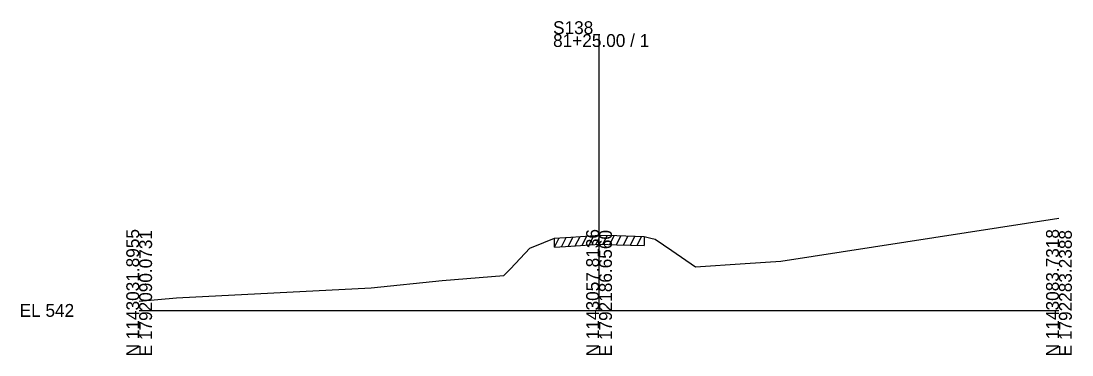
# Model space of a CAD drawing. Extents: x -26 to 1203, y -10 to 19606.
# Drawn here: x -25.7 to 202.8, y 2490.3 to 2562.9 of the extents above; entities that cross this region are included whole.
import ezdxf

# ---------------------------------------------------------------- set-up
doc = ezdxf.new("R2010")
doc.units = 0
for name, color, linetype in [('RD_EX_Driveway', 7, 'Continuous'), ('RD_GPK_XS_Cell', 7, 'Continuous'), ('RD_XS_ExGround', 7, 'Continuous'), ('RD_XS_ExPaveRet', 7, 'Continuous')]:
    doc.layers.add(name, color=color, linetype=linetype)

msp = doc.modelspace()

# ---------------------------------------------------------------- linework, layer by layer
at = {"layer": 'RD_GPK_XS_Cell'}
for p, q in [((100, 2500), (100, 2560.08)), ((0, 2500), (100, 2500)), ((100, 2500), (200, 2500))]:
    msp.add_line(p, q, dxfattribs=at)
at = {"layer": 'RD_XS_ExGround'}
msp.add_lwpolyline([(0, 2502.02), (8.12, 2502.73), (50.45, 2504.88), (65.87, 2506.51), (79.27, 2507.58), (80.78, 2509.06), (84.98, 2513.5), (87.96, 2514.78), (90.32, 2515.73), (93.84, 2515.94), (100.19, 2516.38), (103.89, 2516.29), (109.79, 2516.1), (111.27, 2515.71), (112.23, 2515.48), (115.83, 2513.05), (120.99, 2509.48), (131.78, 2510.19), (139.56, 2510.7), (200, 2520.03)], dxfattribs=at)
at = {"layer": 'RD_XS_ExPaveRet'}
for p, q in [((96.32, 2514.11), (97.36, 2516.18)), ((97.82, 2514.22), (98.86, 2516.29)), ((99.32, 2514.32), (100.35, 2516.38)), ((100.82, 2514.37), (101.81, 2516.34)), ((102.32, 2514.33), (103.31, 2516.31)), ((103.82, 2514.3), (104.8, 2516.26)), ((105.32, 2514.25), (106.3, 2516.21)), ((106.82, 2514.2), (107.8, 2516.16)), ((90.32, 2513.73), (91.35, 2515.79)), ((90.32, 2513.73), (90.32, 2515.73)), ((90.32, 2513.73), (93.84, 2513.94)), ((91.82, 2513.82), (92.85, 2515.88)), ((93.32, 2513.91), (94.35, 2515.97)), ((93.84, 2513.94), (100.19, 2514.38)), ((94.82, 2514.01), (95.86, 2516.08)), ((100.19, 2514.38), (103.89, 2514.29)), ((103.89, 2514.29), (109.79, 2514.1)), ((108.32, 2514.15), (109.3, 2516.11)), ((109.79, 2516.1), (109.79, 2514.1))]:
    msp.add_line(p, q, dxfattribs=at)

# ---------------------------------------------------------------- texts
at = {"layer": 'RD_EX_Driveway'}
msp.add_text('550.18', height=0.0975, rotation=90, dxfattribs=at).set_placement((100.1, 2516.37))
at = {"layer": 'RD_GPK_XS_Cell'}
for s, p in [('S138', (90, 2560.08)), ('81+25.00 / 1', (90, 2557.28)), ('EL 542', (-26, 2498.6))]:
    msp.add_text(s, height=2.8, dxfattribs=at).set_placement(p)
for s, p in [('N 1143031.8955', (0, 2490)), ('E 1792090.0731', (2.8, 2490)), ('N 1143057.8136', (100, 2490)), ('E 1792186.6560', (102.8, 2490)), ('N 1143083.7318', (200, 2490)), ('E 1792283.2388', (202.8, 2490))]:
    msp.add_text(s, height=2.8, rotation=90, dxfattribs=at).set_placement(p)

doc.saveas('drawing.dxf')
